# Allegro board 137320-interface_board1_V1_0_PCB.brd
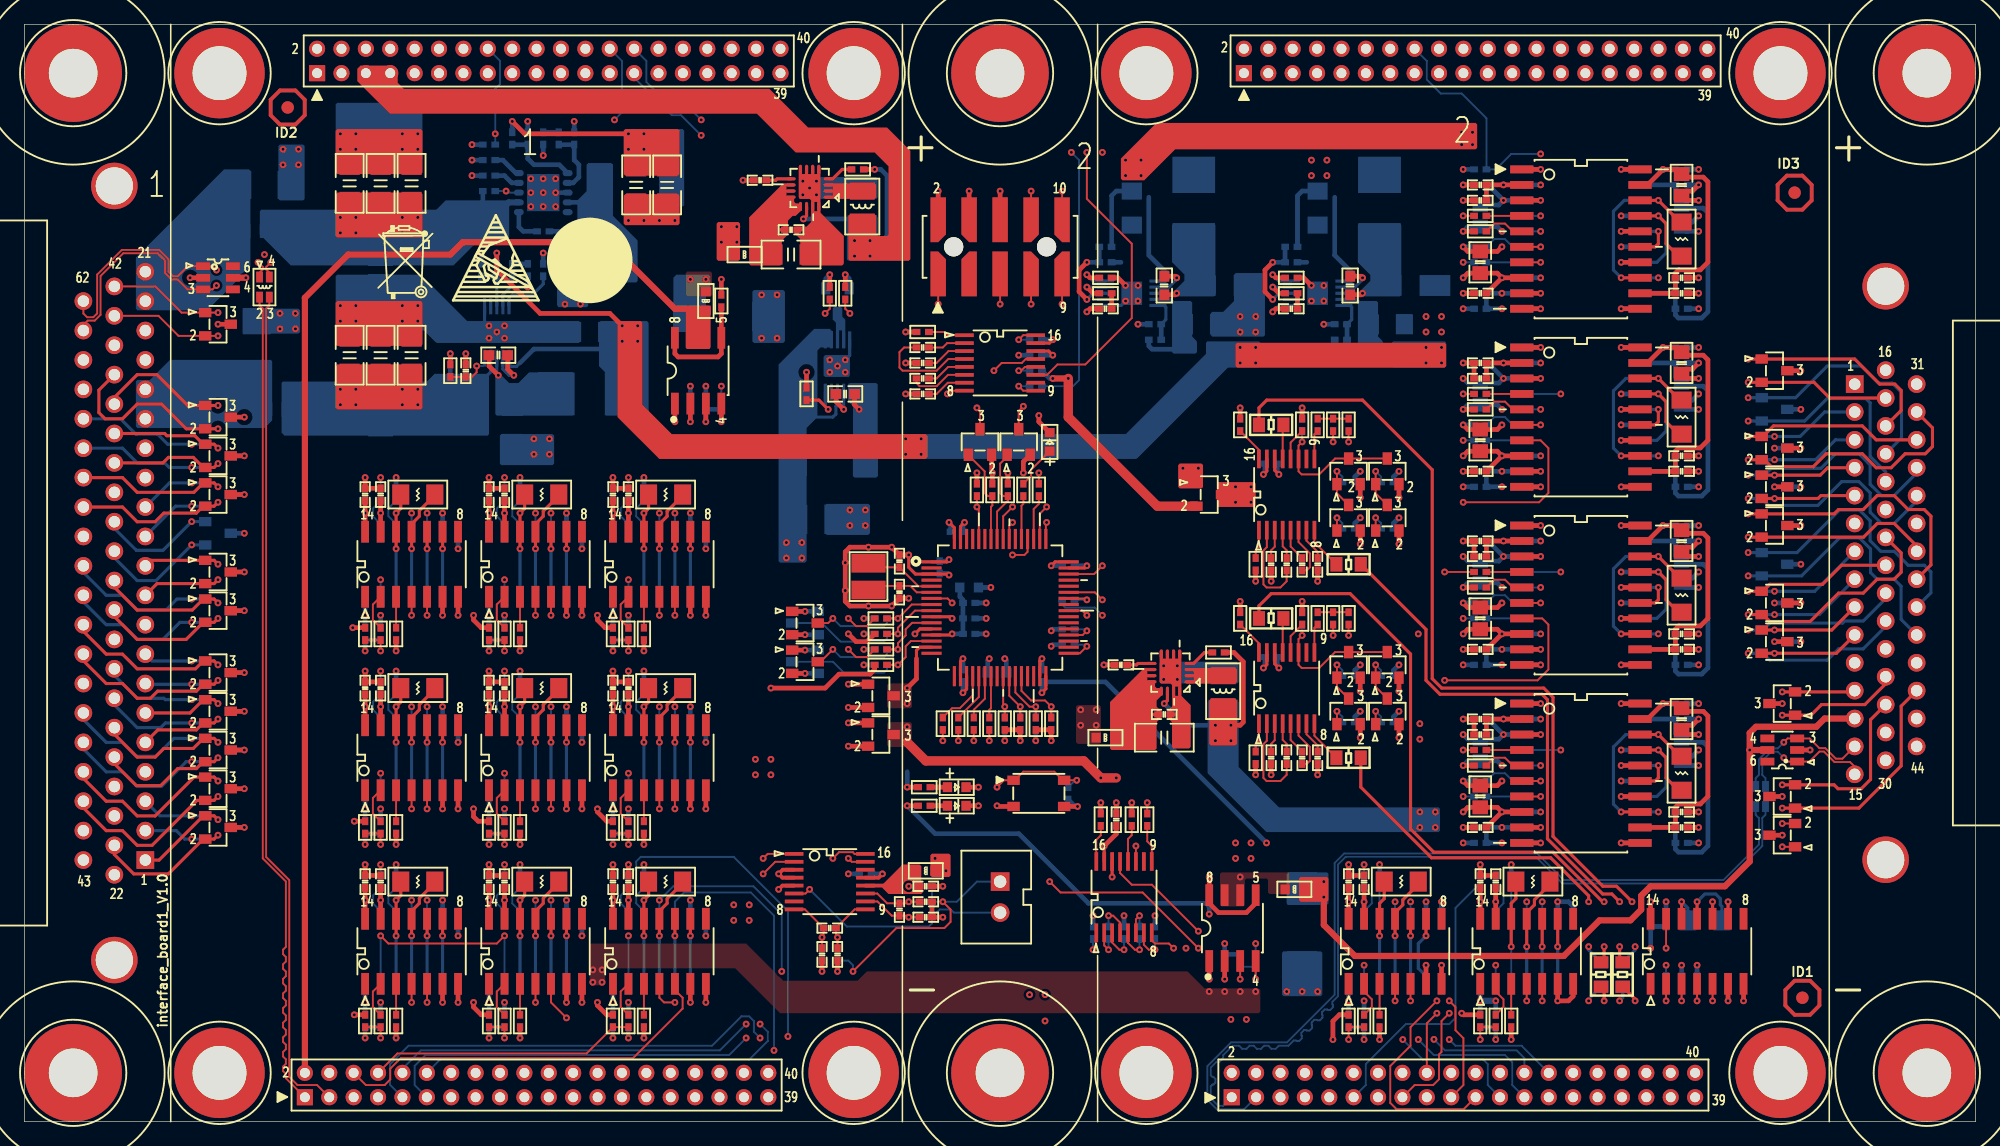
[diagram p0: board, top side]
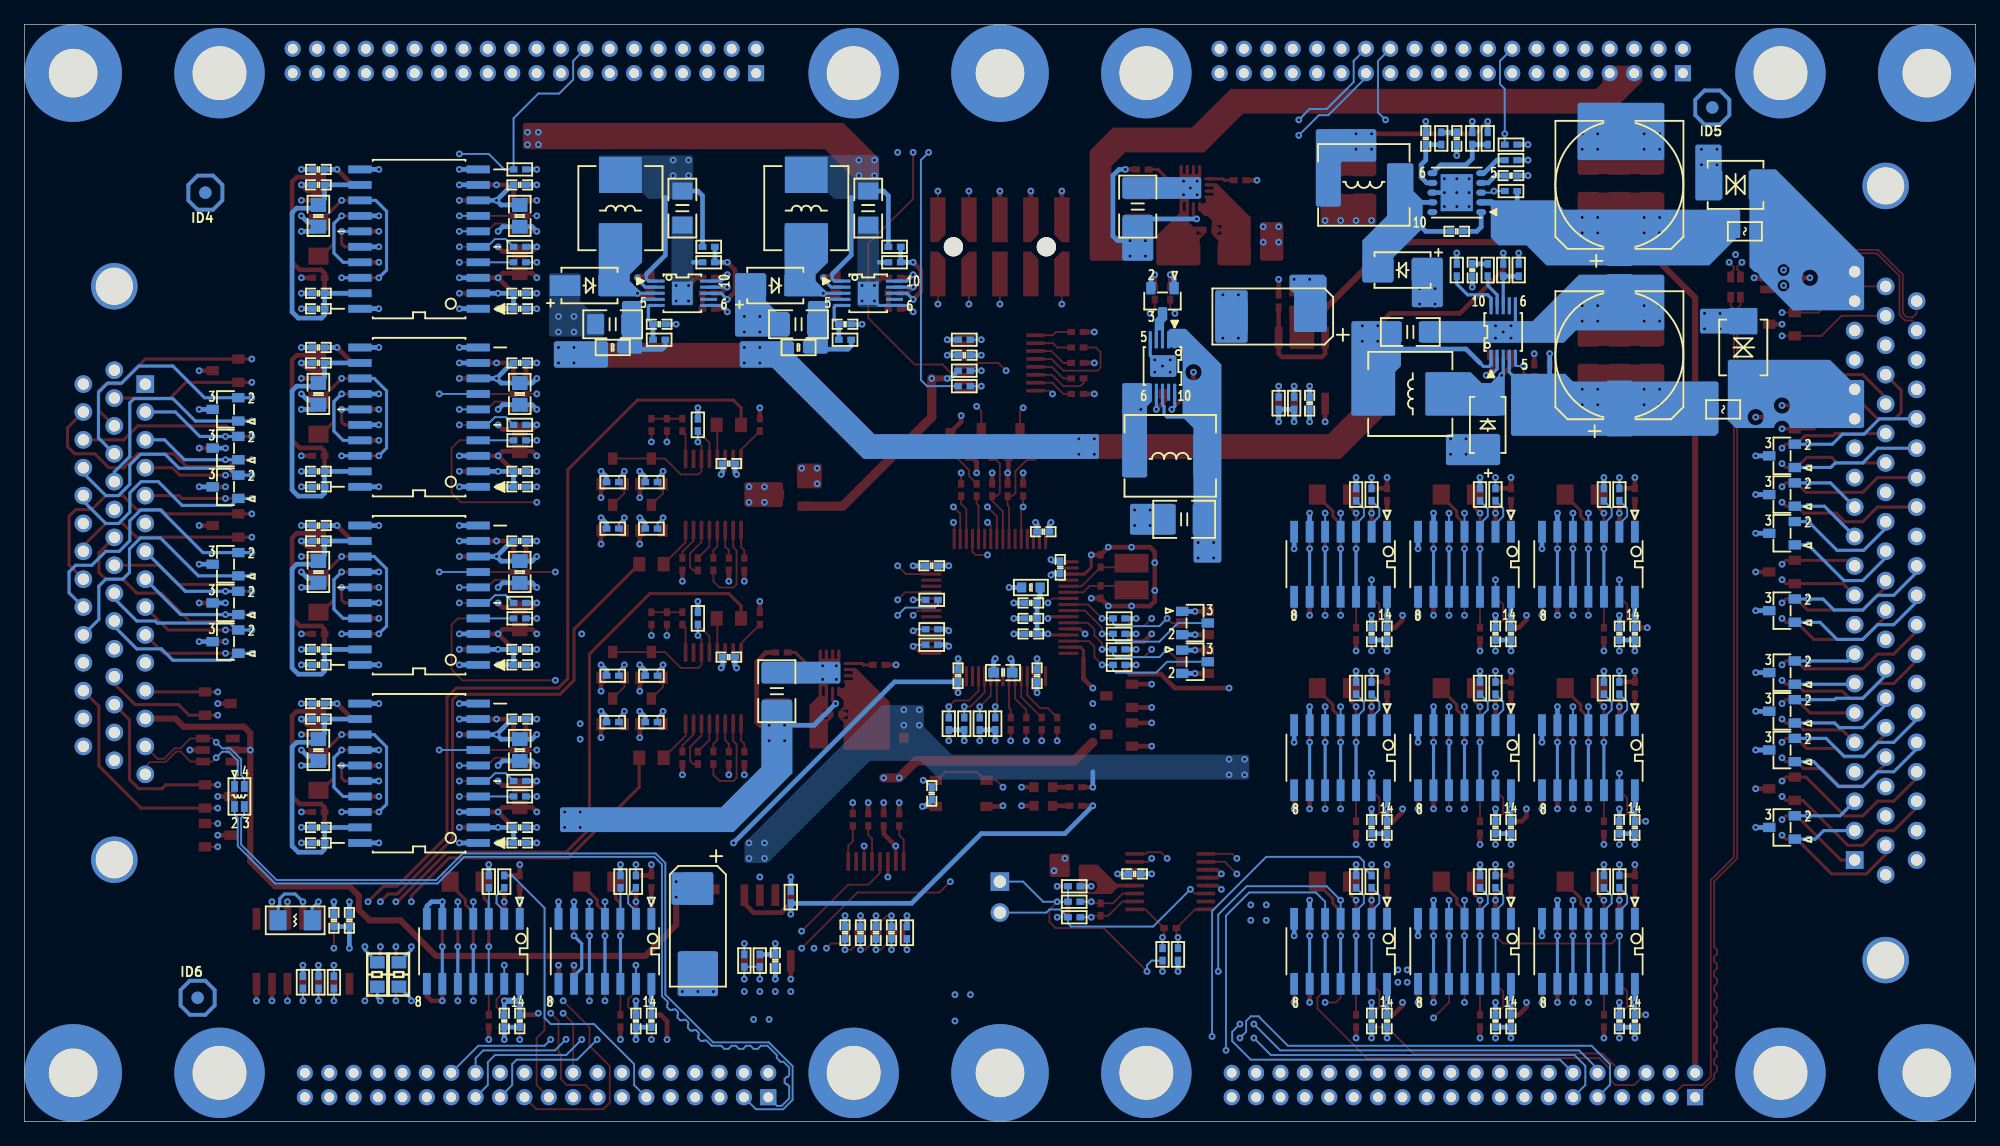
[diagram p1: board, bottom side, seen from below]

Outline 160 x 90 mm; copper layers: TOP, GND02, ART03, ART04, POWER05, BOTTOM. Coordinates in mm from the lower left corner of the outline.
Outline path: 0,90 0,0 160,0 160,90 0,90

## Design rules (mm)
net group DIFFPAIR0: nets CON_MAIN_USB_N CON_MAIN_USB_P
net group DIFFPAIR1: nets MAIN_USB_DN MAIN_USB_DP
net group DIFFPAIR2: nets CON_SPARE_USB_N CON_SPARE_USB_P
net group DIFFPAIR3: nets SPARE_USB_DN SPARE_USB_DP

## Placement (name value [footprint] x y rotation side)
C1  100u  [AEC10_5X10_5-G]  29.21 76.83 90 bottom
C2  0.1u  [C0402]  42.55 73.03 0 bottom
C3  4.7u  [C1206]  31.75 76.96 90 top
C4  4.7u  [C1206]  29.21 76.96 90 top
C5  4.7u  [C1206]  26.67 76.96 90 top
C6  47u  [C1206]  52.7 76.83 270 top
C7  47u  [C1206]  50.16 76.83 270 top
C8  0.01u  [C0402]  42.55 80.64 270 bottom
C9  12p  [C0402]  45.09 80.64 90 bottom
C10  0.01u  [C0402]  38.1 77.6 180 bottom
C11  22u  [C1210]  68.71 75.06 90 bottom
C12  47u  [C1206]  62.87 71.12 0 top
C13  0.1u  [C0402]  62.87 73.15 0 top
C14  160p  [C0402]  60.33 77.22 180 top
C15  0.47u  [C0603]  38.86 62.87 180 top
C16  100u  [AEC10_5X10_5-G]  29.21 62.87 90 bottom
C17  4.7u  [C1206]  31.75 62.87 90 top
C18  4.7u  [C1206]  29.21 62.87 90 top
C19  4.7u  [C1206]  26.67 62.87 90 top
C20  0.1u  [C0402]  36.2 61.59 270 top
C21  47u  [C1206]  46.35 64.77 180 bottom
C22  470p  [C0402]  41.27 69.85 270 bottom
C23  0.47u  [C0603]  108.71 68.58 270 top
C24  4.7u  [C1206]  111.76 65.41 0 bottom
C25  0.1u  [C0402]  107.95 65.41 0 bottom
C26  47u  [C1206]  106.05 74.93 270 bottom
C27  470p  [C0402]  103.89 66.67 180 top
C28  0.47u  [C0603]  67.31 59.69 0 top
C29  22u  [C1210]  64.9 49.4 0 bottom
C30  20p  [C0402]  71.75 45.97 90 top
C31  20p  [C0402]  71.75 43.43 270 top
C32  0.1u  [C0402]  85.6 26.92 270 bottom
C33  0.1u  [C0402]  76.96 36.58 90 bottom
C34  0.01u  [C0402]  77.47 40.01 0 bottom
C35  0.1u  [C0402]  77.47 41.27 0 bottom
C36  1u  [C0402]  77.47 42.55 0 bottom
C37  0.1u  [C0402]  83.44 36.58 90 bottom
C38  0.1u  [C0402]  85.6 45.59 0 bottom
C39  0.1u  [C0402]  76.45 48.39 0 bottom
C40  0.1u  [C0402]  75.06 45.47 270 bottom
C41  4.7u  [C0603]  79.76 36.83 0 bottom
C42  0.01u  [C0402]  73.91 18.03 0 top
C43  0.1u  [C0402]  71.75 17.4 90 top
C44  0.1u  [C0402]  133.35 16.51 270 bottom
C45  0.1u  [C0402]  134.62 16.51 270 bottom
C46  0.01u  [C0402]  73.91 16.76 0 top
C47  0.01u  [C0402]  66.67 13.72 270 top
C48  0.1u  [C0402]  66.04 15.88 0 top
C49  0.01u  [C0402]  65.41 13.72 270 top
C50  0.1u  [C0402]  73.91 19.3 0 top
C51  0.1u  [C0402]  68.96 20.32 180 bottom
C52  22u  [C1210]  98.3 35.31 90 bottom
C53  47u  [C1206]  93.47 31.5 0 top
C54  0.1u  [C0402]  93.47 33.4 0 top
C55  160p  [C0402]  89.92 37.47 180 top
C56  0.47u  [C0603]  93.47 68.58 270 top
C57  4.7u  [C1206]  96.52 65.41 0 bottom
C58  470p  [C0402]  88.65 66.67 180 top
C59  0.1u  [C0402]  92.71 65.41 0 bottom
C60  47u  [C1206]  90.81 74.93 270 bottom
C61  0.1u  [C0402]  29.21 51.44 90 top
C62  0.1u  [C0402]  27.94 51.44 90 top
C63  0.1u  [C0402]  29.21 40.01 270 bottom
C64  0.1u  [C0402]  27.94 40.01 270 bottom
C65  0.1u  [C0402]  39.37 51.44 90 top
C66  0.1u  [C0402]  38.1 51.44 90 top
C67  0.1u  [C0402]  39.37 40.01 270 bottom
C68  0.1u  [C0402]  38.1 40.01 270 bottom
C69  0.1u  [C0402]  49.53 51.44 90 top
C70  0.1u  [C0402]  48.26 51.44 90 top
C71  0.1u  [C0402]  48.26 40.01 270 bottom
C72  0.1u  [C0402]  49.53 40.01 270 bottom
C73  0.1u  [C0402]  29.21 35.56 90 top
C74  0.1u  [C0402]  27.94 35.56 90 top
C75  0.1u  [C0402]  29.21 24.13 270 bottom
C76  0.1u  [C0402]  27.94 24.13 270 bottom
C77  0.1u  [C0402]  39.37 35.56 90 top
C78  0.1u  [C0402]  38.1 35.56 90 top
C79  0.1u  [C0402]  38.1 24.13 270 bottom
C80  0.1u  [C0402]  39.37 24.13 270 bottom
C81  0.1u  [C0402]  49.53 35.56 90 top
C82  0.1u  [C0402]  48.26 35.56 90 top
C83  0.1u  [C0402]  49.53 24.13 270 bottom
C84  0.1u  [C0402]  48.26 24.13 270 bottom
C85  0.1u  [C0402]  29.21 19.68 90 top
C86  0.1u  [C0402]  27.94 19.68 90 top
C87  0.1u  [C0402]  29.21 8.26 270 bottom
C88  0.1u  [C0402]  27.94 8.26 270 bottom
C89  0.1u  [C0402]  39.37 19.68 90 top
C90  0.1u  [C0402]  38.1 19.68 90 top
C91  0.1u  [C0402]  39.37 8.26 270 bottom
C92  0.1u  [C0402]  38.1 8.26 270 bottom
C93  0.1u  [C0402]  49.53 19.68 90 top
C94  0.1u  [C0402]  48.26 19.68 90 top
C95  0.1u  [C0402]  48.26 8.26 270 bottom
C96  0.1u  [C0402]  49.53 8.26 270 bottom
C129  10u  [C0805]  119.38 26.67 90 top
C130  0.1u  [C0402]  119.38 33.02 180 top
C131  0.01u  [C0402]  119.38 24.13 180 top
C132  0.1u  [C0402]  119.38 31.75 180 top
C133  10u  [C0805]  135.89 33.02 270 top
C134  0.1u  [C0402]  135.89 25.4 0 top
C135  0.01u  [C0402]  135.89 24.13 0 top
C136  0.1u  [C0402]  135.89 34.29 0 bottom
C137  0.1u  [C0402]  119.38 24.13 180 bottom
C138  10u  [C0805]  119.38 30.48 270 bottom
C139  0.1u  [C0402]  119.38 22.86 180 bottom
C140  0.01u  [C0402]  119.38 33.02 180 bottom
C141  10u  [C0805]  135.89 30.48 270 bottom
C142  0.1u  [C0402]  135.89 33.02 0 bottom
C143  0.01u  [C0402]  135.89 22.86 0 bottom
C144  0.1u  [C0402]  135.89 24.13 0 bottom
C145  10u  [C0805]  119.38 74.3 270 bottom
C146  0.1u  [C0402]  119.38 67.94 180 bottom
C147  0.01u  [C0402]  119.38 76.83 180 bottom
C148  0.1u  [C0402]  119.38 66.67 180 bottom
C149  10u  [C0805]  135.89 74.3 270 bottom
C150  0.1u  [C0402]  135.89 67.94 0 bottom
C151  0.01u  [C0402]  135.89 66.67 0 bottom
C152  0.1u  [C0402]  135.89 76.83 0 bottom
C153  10u  [C0805]  119.38 70.48 90 top
C154  0.1u  [C0402]  119.38 76.83 180 top
C155  0.01u  [C0402]  119.38 67.94 180 top
C156  0.1u  [C0402]  119.38 75.56 180 top
C157  10u  [C0805]  135.89 76.83 270 top
C158  0.1u  [C0402]  135.89 78.11 0 bottom
C159  0.01u  [C0402]  135.89 67.94 0 top
C160  0.1u  [C0402]  135.89 69.22 0 top
C161  10u  [C0805]  119.38 41.27 90 top
C162  0.1u  [C0402]  119.38 46.35 180 top
C163  0.01u  [C0402]  119.38 38.73 180 top
C164  0.1u  [C0402]  119.38 47.62 180 top
C165  10u  [C0805]  135.89 47.62 270 top
C166  0.1u  [C0402]  135.89 48.9 0 bottom
C167  0.01u  [C0402]  135.89 38.73 0 top
C168  0.1u  [C0402]  135.89 40.01 0 top
C169  10u  [C0805]  119.38 45.09 270 bottom
C170  0.01u  [C0402]  119.38 47.62 180 bottom
C171  0.1u  [C0402]  119.38 38.73 180 bottom
C172  0.1u  [C0402]  119.38 37.47 180 bottom
C173  10u  [C0805]  135.89 45.09 270 bottom
C174  0.1u  [C0402]  135.89 38.73 0 bottom
C175  0.01u  [C0402]  135.89 37.47 0 bottom
C176  0.1u  [C0402]  135.89 47.62 0 bottom
C177  10u  [C0805]  119.38 55.88 90 top
C178  0.1u  [C0402]  119.38 60.96 180 top
C179  0.01u  [C0402]  119.38 53.34 180 top
C180  0.1u  [C0402]  119.38 62.23 180 top
C181  10u  [C0805]  135.89 62.23 270 top
C182  0.1u  [C0402]  135.89 63.5 0 bottom
C183  0.01u  [C0402]  135.89 53.34 0 top
C184  0.1u  [C0402]  135.89 54.61 0 top
C185  10u  [C0805]  119.38 59.69 270 bottom
C186  0.1u  [C0402]  119.38 52.07 180 bottom
C187  0.01u  [C0402]  119.38 62.23 180 bottom
C188  0.1u  [C0402]  119.38 53.34 180 bottom
C189  10u  [C0805]  135.89 59.69 270 bottom
C190  0.1u  [C0402]  135.89 53.34 0 bottom
C191  0.01u  [C0402]  135.89 52.07 0 bottom
C192  0.1u  [C0402]  135.89 62.23 0 bottom
C193  0.1u  [C0402]  82.93 62.87 0 bottom
C194  0.1u  [C0402]  73.66 63.5 180 top
C195  0.1u  [C0402]  73.66 60.96 180 top
C196  0.1u  [C0402]  73.66 59.69 180 top
C197  0.1u  [C0402]  73.66 62.23 180 top
C198  0.1u  [C0402]  89.53 24.77 90 top
C199  0.1u  [C0402]  88.9 15.49 90 bottom
C200  0.1u  [C0402]  91.44 15.49 90 bottom
C201  0.1u  [C0402]  92.71 15.49 90 bottom
C202  0.1u  [C0402]  90.17 15.49 90 bottom
C203  220u  [TC7343]  57.78 66.04 0 bottom
C204  0.1u  [C0402]  54.61 58.93 90 bottom
C205  220u  [TC7343]  104.78 15.88 270 bottom
C206  0.1u  [C0402]  98.42 13.21 90 bottom
C207  0.1u  [C0402]  109.86 19.68 90 top
C208  0.1u  [C0402]  109.86 8.26 270 bottom
C209  0.1u  [C0402]  108.58 19.68 90 top
C210  0.1u  [C0402]  108.58 8.26 270 bottom
C211  0.1u  [C0402]  120.65 19.68 90 top
C212  0.1u  [C0402]  120.65 8.26 270 bottom
C213  0.1u  [C0402]  119.38 19.68 90 top
C214  0.1u  [C0402]  119.38 8.26 270 bottom
C215  0.1u  [C0402]  106.05 29.84 270 top
C216  0.1u  [C0402]  102.23 38.1 0 bottom
C217  0.1u  [C0402]  103.5 29.84 90 top
C218  0.1u  [C0402]  104.78 29.84 270 top
C219  0.1u  [C0402]  102.23 29.84 270 top
C220  0.1u  [C0402]  106.05 45.72 270 top
C221  0.1u  [C0402]  102.23 53.98 0 bottom
C222  0.1u  [C0402]  103.5 45.72 90 top
C223  0.1u  [C0402]  104.78 45.72 270 top
C224  0.1u  [C0402]  102.23 45.72 270 top
D1  SMBJ36CA  [DO-214AA_SMB]  19.68 76.83 0 bottom
D2  B350A-13-F  [SMA]  46.99 69.85 0 bottom
D3  APT1608SYCK  [D0603]  76.45 27.43 0 top
D4  SMBJ36CA  [DO-214AA_SMB]  19.05 63.5 90 bottom
D5  B350A-13-F  [SMA]  40.01 57.15 90 bottom
D6  APT1608SYCK  [D0603]  76.45 25.91 0 top
D7  B350A-13-F  [SMA]  113.67 68.58 180 bottom
D8  BAV170Q-7-F  [SOT23-3-095-3X1_4]  66.67 67.31 0 bottom
D9  BAT54S  [SOT23-3-095-3X1_4]  64.01 40.89 270 top
D10  BAT54S  [SOT23-3-095-3X1_4]  64.01 40.89 270 bottom
D11  BAT54S  [SOT23-3-095-3X1_4]  70.23 31.75 270 top
D12  BAT54S  [SOT23-3-095-3X1_4]  70.23 34.92 270 top
D13  BAT54S  [SOT23-3-095-3X1_4]  64.01 37.72 270 bottom
D14  BAT54S  [SOT23-3-095-3X1_4]  64.01 37.72 270 top
D15  APT1608SYCK  [D0603]  84.07 55.75 90 top
D16  CDSOT23-T24CAN  [SOT23-3-095-3X1_4]  144.15 34.29 90 top
D17  CDSOT23-T24CAN  [SOT23-3-095-3X1_4]  144.15 26.67 90 top
D18  B350A-13-F  [SMA]  98.42 68.58 180 bottom
D19  CDSOT23-T24CAN  [SOT23-3-095-3X1_4]  15.88 57.78 270 top
D20  CDSOT23-T24CAN  [SOT23-3-095-3X1_4]  15.88 54.61 270 top
D21  CDSOT23-T24CAN  [SOT23-3-095-3X1_4]  15.88 54.61 90 bottom
D22  CDSOT23-T24CAN  [SOT23-3-095-3X1_4]  15.88 51.44 270 top
D23  CDSOT23-T24CAN  [SOT23-3-095-3X1_4]  15.88 51.44 90 bottom
D24  CDSOT23-T24CAN  [SOT23-3-095-3X1_4]  15.88 45.09 270 top
D25  CDSOT23-T24CAN  [SOT23-3-095-3X1_4]  15.88 48.26 90 bottom
D26  CDSOT23-T24CAN  [SOT23-3-095-3X1_4]  15.88 41.91 270 top
D27  CDSOT23-T24CAN  [SOT23-3-095-3X1_4]  15.88 41.91 90 bottom
D28  CDSOT23-T24CAN  [SOT23-3-095-3X1_4]  15.88 36.83 270 top
D29  CDSOT23-T24CAN  [SOT23-3-095-3X1_4]  15.88 36.83 90 bottom
D30  CDSOT23-T24CAN  [SOT23-3-095-3X1_4]  15.88 33.66 270 top
D31  CDSOT23-T24CAN  [SOT23-3-095-3X1_4]  15.88 33.66 90 bottom
D32  CDSOT23-T24CAN  [SOT23-3-095-3X1_4]  15.88 30.48 270 top
D33  CDSOT23-T24CAN  [SOT23-3-095-3X1_4]  15.88 30.48 90 bottom
D34  CDSOT23-T24CAN  [SOT23-3-095-3X1_4]  15.88 27.3 270 top
D35  CDSOT23-T24CAN  [SOT23-3-095-3X1_4]  15.88 24.13 90 bottom
D36  CDSOT23-T24CAN  [SOT23-3-095-3X1_4]  15.88 24.13 270 top
D41  CDSOT23-T24CAN  [SOT23-3-095-3X1_4]  143.51 39.37 90 bottom
D42  CDSOT23-T24CAN  [SOT23-3-095-3X1_4]  143.51 42.55 270 top
D43  CDSOT23-T24CAN  [SOT23-3-095-3X1_4]  143.51 58.42 90 bottom
D44  CDSOT23-T24CAN  [SOT23-3-095-3X1_4]  143.51 61.59 270 top
D45  CDSOT23-T24CAN  [SOT23-3-095-3X1_4]  143.51 45.72 90 bottom
D46  CDSOT23-T24CAN  [SOT23-3-095-3X1_4]  143.51 48.9 270 top
D47  CDSOT23-T24CAN  [SOT23-3-095-3X1_4]  143.51 52.07 90 bottom
D48  CDSOT23-T24CAN  [SOT23-3-095-3X1_4]  143.51 55.24 270 top
D49  CDSOT23-T24CAN  [SOT23-3-095-3X1_4]  15.88 65.41 270 top
D50  CDSOT23-T24CAN  [SOT23-3-095-3X1_4]  144.15 23.5 90 top
D51  CDSOT23-T24CAN  [SOT23-3-095-3X1_4]  143.51 39.37 270 top
D52  CDSOT23-T24CAN  [SOT23-3-095-3X1_4]  143.51 42.55 90 bottom
D53  CDSOT23-T24CAN  [SOT23-3-095-3X1_4]  143.51 55.24 90 bottom
D54  CDSOT23-T24CAN  [SOT23-3-095-3X1_4]  143.51 52.07 270 top
D55  BAV170Q-7-F  [SOT23-3-095-3X1_4]  97.16 51.44 270 top
F1  0467003  [F0603]  18.92 73.03 0 bottom
F2  0467003  [F0603]  20.7 58.42 0 bottom
FB1  BLM18PG121SH1D  [FB0603]  59.05 71.12 0 top
FB2  BLM18PG121SH1D  [FB0603]  111.76 63.5 180 bottom
FB3  BLM18PG121SH1D  [FB0603]  77.47 43.81 0 bottom
FB4  BLM18PG121SH1D  [FB0603]  73.91 20.57 180 top
FB5  BLM18PG121SH1D  [FB0603]  88.65 31.5 0 top
FB6  BLM18PG121SH1D  [FB0603]  96.52 63.5 180 bottom
FB7  BLM18PG121SH1D  [FB0603]  55.88 67.31 270 top
FB8  BLM18PG121SH1D  [FB0603]  104.14 19.05 180 top
H1  MH-7R4D3R2  [HOLE315-157]  4 86 0 top
H2  MH-7R4D3R2  [HOLE315-157]  4 4 0 top
H3  MH-7R4D3R2  [HOLE315-157]  80 86 0 top
H4  MH-7R4D3R2  [HOLE315-157]  80 4 0 top
H5  MH-7R4D3R2  [HOLE315-157]  156 86 0 top
H6  MH-7R4D3R2  [HOLE315-157]  156 4 0 top
J1  181-M62-213R141  [DB62-3CF]  -0.7 45 270 top
J2  181-M44-213R141  [DB44-3CF]  160.7 45 90 top
J3  791077069  [HD40-2_0-40_19X4_19-H4_44]  43 87 0 top
J4  791077069  [HD40-2_0-40_19X4_19-H4_44]  42 3 0 top
J5  791077069  [HD40-2_0-40_19X4_19-H4_44]  119 87 0 top
J6  791077069  [HD40-2_0-40_19X4_19-H4_44]  118 3 0 top
J8  0901311081  [SIP2-2_54]  80.01 18.41 90 top
J9  15-91-0100  [SHD10-2_54]  80.01 71.75 0 top
L1  15uH  [L7567]  50.16 76.83 0 bottom
L2  2.2uH  [L1008]  68.71 75.06 270 top
L3  6.8uH  [IND_74437349047]  46.35 59.69 0 bottom
L4  6.8uH  [IND_74437349047]  111.12 74.93 90 bottom
L5  15uH  [L7567]  66.04 54.61 180 bottom
L6  2.2uH  [L1008]  98.3 35.31 270 top
L7  6.8uH  [IND_74437349047]  95.89 74.93 90 bottom
L8  ACM2012H  [L4-0805]  19.68 68.45 270 top
L9  ACM2012H  [L4-0805]  142.37 26.67 270 bottom
NOREF  -  []  459.86 210.4 0 top
NOREF#2  -  []  459.86 202.78 0 top
NOREF#3  -  []  247.78 -1.91 0 top
NOREF#4  -  []  434.46 210.4 0 top
NOREF#5  -  []  37.97 70.36 0 top
NOREF#6  -  []  257.81 174.75 0 top
NOREF#7  -  [unnamed#2]  21.59 83.19 0 top
NOREF#8  -  []  46.86 70.87 0 top
NOREF#9  -  []  434.46 195.16 0 top
NOREF#10  -  []  -19.05 -43.18 0 top
NOREF#11  -  [unnamed#2]  145.8 10.16 0 top
NOREF#12  -  []  459.86 195.16 0 top
NOREF#13  -  []  33.78 70.61 0 top
NOREF#14  -  []  281.94 109.98 0 top
NOREF#15  -  []  434.46 202.78 0 top
NOREF#16  -  [unnamed#2]  145.16 76.2 0 top
NOREF#17  -  []  247.9 52.96 0 top
NOREF#18  -  [unnamed#2]  145.8 10.16 180 bottom
NOREF#19  -  [unnamed#2]  145.16 76.2 180 bottom
NOREF#20  -  [unnamed#2]  21.59 83.19 180 bottom
Q1  2N7002ET1G  [SOT23-3-095-3X1_4]  81.53 55.75 0 top
Q2  2N7002ET1G  [SOT23-3-095-3X1_4]  78.36 55.75 0 top
Q3  2N7002ET1G  [SOT23-3-095-3X1_4]  111.76 33.66 0 top
Q4  2N7002ET1G  [SOT23-3-095-3X1_4]  111.76 37.47 0 top
Q5  2N7002ET1G  [SOT23-3-095-3X1_4]  108.58 33.66 0 top
Q6  2N7002ET1G  [SOT23-3-095-3X1_4]  108.58 37.47 0 top
Q7  2N7002ET1G  [SOT23-3-095-3X1_4]  111.76 49.53 0 top
Q8  2N7002ET1G  [SOT23-3-095-3X1_4]  111.76 53.34 0 top
Q9  2N7002ET1G  [SOT23-3-095-3X1_4]  108.58 49.53 0 top
Q10  2N7002ET1G  [SOT23-3-095-3X1_4]  108.58 53.34 0 top
R1  4.7K  [R0402]  38.1 80.14 0 bottom
R2  4.7K  [R0402]  119.38 78.11 0 bottom
R3  10K  [R0402]  38.1 76.33 0 bottom
R4  10K  [R0402]  43.81 80.64 270 bottom
R5  60.4k  [R0402]  40.01 80.64 270 bottom
R6  4.7K  [R0402]  73.79 27.43 0 top
R7  200k  [R0402]  38.1 78.87 180 bottom
R8  11.5k  [R0402]  41.27 80.64 90 bottom
R9  4.7K  [R0402]  68.33 78.11 0 top
R10  10K  [R0402]  34.92 61.59 270 top
R11  16.2k  [R0402]  40.01 69.85 90 bottom
R12  536k  [R0402]  38.73 69.85 270 bottom
R13  4.7K  [R0402]  73.79 25.91 0 top
R14  68.1k  [R0402]  42.55 69.85 90 bottom
R15  100K  [R0402]  37.47 69.85 90 bottom
R16  10K  [R0402]  107.95 64.14 0 bottom
R17  20k  [R0402]  103.89 67.94 0 top
R18  316k  [R0402]  103.89 71.75 180 bottom
R19  68.1k  [R0402]  103.89 69.22 0 top
R20  100K  [R0402]  103.89 70.48 0 bottom
R21  0  [R0402]  66.04 67.94 90 top
R22  0  [R0402]  67.31 67.94 90 top
R23  215k  [R0402]  64.14 59.69 90 top
R24  1K  [R0402]  70.23 41.27 0 bottom
R25  10K  [R0402]  70.23 41.27 0 top
R26  10K  [R0402]  70.23 40.01 0 top
R27  10K  [R0402]  70.23 40.01 0 bottom
R28  33  [R0402]  75.31 32.64 90 top
R29  33  [R0402]  76.58 32.64 90 top
R30  1K  [R0402]  70.23 38.73 0 bottom
R31  10K  [R0402]  70.23 38.73 0 top
R32  10K  [R0402]  70.23 37.47 0 top
R33  0  [R0402]  77.85 32.64 90 top
R34  33  [R0402]  79.12 32.64 90 top
R35  10K  [R0402]  70.23 37.47 0 bottom
R36  33  [R0402]  85.6 42.8 180 bottom
R37  10K  [R0402]  85.6 39.12 0 bottom
R38  10K  [R0402]  78.11 51.82 90 top
R39  10K  [R0402]  85.6 40.39 0 bottom
R40  33  [R0402]  83.19 51.82 270 top
R41  4.7K  [R0402]  81.92 51.82 90 top
R42  4.7K  [R0402]  80.64 51.82 90 top
R43  4.7K  [R0402]  79.38 51.82 90 top
R44  4.7K  [R0402]  135.89 11.43 90 bottom
R45  120  [R1206]  137.79 16.51 0 bottom
R46  33  [R0402]  134.62 11.43 270 bottom
R47  1K  [R0402]  73.91 18.03 180 bottom
R48  1K  [R0402]  73.91 16.76 180 bottom
R49  1K  [R0402]  137.16 11.43 90 bottom
R50  1K  [R0402]  66.67 13.72 90 bottom
R51  1.65k  [R0402]  73.91 19.3 180 bottom
R52  1K  [R0402]  65.41 13.72 90 bottom
R53  4.7K  [R0402]  97.92 38.48 0 top
R54  10K  [R0402]  92.71 64.14 0 bottom
R55  20k  [R0402]  88.65 67.94 0 top
R56  316k  [R0402]  88.65 71.75 180 bottom
R57  68.1k  [R0402]  88.65 69.22 0 top
R58  100K  [R0402]  88.65 70.48 0 bottom
R59  4.7K  [R0402]  30.48 40.01 270 top
R60  120  [R1206]  32.26 51.44 0 top
R61  2.7k  [R0402]  29.21 40.01 90 top
R62  4.7K  [R0402]  27.94 40.01 90 top
R63  4.7K  [R0402]  30.48 51.44 90 bottom
R64  33  [R0402]  29.21 51.44 270 bottom
R65  4.7K  [R0402]  40.64 40.01 270 top
R66  120  [R1206]  42.42 51.44 0 top
R67  4.7K  [R0402]  38.1 40.01 90 top
R68  2.7k  [R0402]  39.37 40.01 90 top
R69  4.7K  [R0402]  40.64 51.44 90 bottom
R70  33  [R0402]  39.37 51.44 270 bottom
R71  4.7K  [R0402]  50.8 40.01 270 top
R72  120  [R1206]  52.58 51.44 0 top
R73  4.7K  [R0402]  48.26 40.01 90 top
R74  2.7k  [R0402]  49.53 40.01 90 top
R75  4.7K  [R0402]  50.8 51.44 90 bottom
R76  33  [R0402]  49.53 51.44 270 bottom
R77  4.7K  [R0402]  30.48 24.13 270 top
R78  4.7K  [R0402]  27.94 24.13 90 top
R79  2.7k  [R0402]  29.21 24.13 90 top
R80  120  [R1206]  32.26 35.56 0 top
R81  4.7K  [R0402]  30.48 35.56 90 bottom
R82  33  [R0402]  29.21 35.56 270 bottom
R83  4.7K  [R0402]  40.64 24.13 270 top
R84  2.7k  [R0402]  39.37 24.13 90 top
R85  120  [R1206]  42.42 35.56 0 top
R86  4.7K  [R0402]  38.1 24.13 90 top
R87  4.7K  [R0402]  40.64 35.56 90 bottom
R88  33  [R0402]  39.37 35.56 270 bottom
R89  4.7K  [R0402]  50.8 24.13 270 top
R90  2.7k  [R0402]  49.53 24.13 90 top
R91  120  [R1206]  52.58 35.56 0 top
R92  4.7K  [R0402]  48.26 24.13 90 top
R93  4.7K  [R0402]  50.8 35.56 90 bottom
R94  33  [R0402]  49.53 35.56 270 bottom
R95  4.7K  [R0402]  30.48 8.26 270 top
R96  120  [R1206]  32.26 19.68 0 top
R97  4.7K  [R0402]  27.94 8.26 90 top
R98  2.7k  [R0402]  29.21 8.26 90 top
R99  4.7K  [R0402]  30.48 19.68 90 bottom
R100  33  [R0402]  29.21 19.68 270 bottom
R101  4.7K  [R0402]  40.64 8.26 270 top
R102  120  [R1206]  42.42 19.68 0 top
R103  4.7K  [R0402]  38.1 8.26 90 top
R104  2.7k  [R0402]  39.37 8.26 90 top
R105  4.7K  [R0402]  40.64 19.68 90 bottom
R106  33  [R0402]  39.37 19.68 270 bottom
R107  4.7K  [R0402]  50.8 8.26 270 top
R108  2.7k  [R0402]  49.53 8.26 90 top
R109  120  [R1206]  52.58 19.68 0 top
R110  4.7K  [R0402]  48.26 8.26 90 top
R111  4.7K  [R0402]  50.8 19.68 90 bottom
R112  33  [R0402]  49.53 19.68 270 bottom
R123  33  [R0402]  119.38 30.48 0 top
R124  120  [R1206]  135.89 28.57 270 top
R125  4.7K  [R0402]  119.38 29.21 180 top
R126  33  [R0402]  119.38 26.67 0 bottom
R127  4.7K  [R0402]  119.38 27.94 180 bottom
R128  33  [R0402]  119.38 70.48 0 bottom
R129  120  [R1206]  135.89 72.39 270 top
R130  4.7K  [R0402]  119.38 71.75 180 bottom
R131  33  [R0402]  119.38 74.3 0 top
R132  4.7K  [R0402]  119.38 73.03 180 top
R133  33  [R0402]  119.38 45.09 0 top
R134  120  [R1206]  135.89 43.18 270 top
R135  4.7K  [R0402]  119.38 43.81 180 top
R136  33  [R0402]  119.38 41.27 0 bottom
R137  4.7K  [R0402]  119.38 42.55 180 bottom
R138  33  [R0402]  119.38 59.69 0 top
R139  120  [R1206]  135.89 57.78 270 top
R140  4.7K  [R0402]  119.38 58.42 180 top
R141  33  [R0402]  119.38 55.88 0 bottom
R142  4.7K  [R0402]  119.38 57.15 180 bottom
R143  10K  [R0402]  82.93 61.59 180 bottom
R144  10K  [R0402]  82.93 64.14 180 bottom
R145  33  [R0402]  82.93 60.33 180 bottom
R146  10K  [R0402]  73.66 64.77 180 top
R147  10K  [R0402]  88.27 24.77 270 top
R148  10K  [R0402]  90.81 24.77 270 top
R149  33  [R0402]  92.08 24.77 270 top
R150  10K  [R0402]  87.63 15.49 90 bottom
R151  10K  [R0402]  57.15 67.31 90 top
R152  0  [R0402]  57.15 58.93 90 bottom
R153  4.7K  [R0402]  55.88 58.93 270 bottom
R154  10K  [R0402]  97.16 18.41 270 bottom
R155  0  [R0402]  100.97 13.21 90 bottom
R156  4.7K  [R0402]  99.69 13.21 270 bottom
R157  4.7K  [R0402]  80.39 32.64 90 bottom
R158  4.7K  [R0402]  80.39 32.64 270 top
R159  4.7K  [R0402]  81.66 32.64 90 bottom
R160  4.7K  [R0402]  81.66 32.64 270 top
R161  4.7K  [R0402]  82.93 32.64 90 bottom
R162  4.7K  [R0402]  82.93 32.64 270 top
R163  4.7K  [R0402]  84.2 32.64 90 bottom
R164  4.7K  [R0402]  84.2 32.64 270 top
R165  4.7K  [R0402]  108.58 8.26 90 top
R166  4.7K  [R0402]  111.12 19.68 90 bottom
R167  4.7K  [R0402]  111.12 8.26 270 top
R168  33  [R0402]  109.86 19.68 270 bottom
R169  2.7k  [R0402]  109.86 8.26 90 top
R170  120  [R1206]  112.9 19.68 0 top
R171  4.7K  [R0402]  121.92 19.68 90 bottom
R172  4.7K  [R0402]  121.92 8.26 270 top
R173  33  [R0402]  120.65 19.68 270 bottom
R174  2.7k  [R0402]  120.65 8.26 90 top
R175  120  [R1206]  123.7 19.68 0 top
R176  4.7K  [R0402]  119.38 8.26 90 top
R177  10K  [R0402]  100.97 29.84 270 top
R178  10K  [R0402]  104.78 41.27 270 top
R179  10K  [R0402]  99.69 41.27 270 top
R180  33  [R0402]  106.05 41.27 270 top
R185  0  [R0402]  107.31 41.27 90 top
R186  0  [R0402]  108.58 41.27 90 top
R187  4.7K  [R0402]  111.76 36.58 0 bottom
R188  4.7K  [R0402]  104.78 41.27 90 bottom
R189  4.7K  [R0402]  108.58 36.58 0 bottom
R190  4.7K  [R0402]  111.76 32.77 180 bottom
R191  4.7K  [R0402]  108.58 32.77 180 bottom
R193  60.4  [R0805]  102.23 41.27 180 top
R194  60.4  [R0805]  108.58 29.84 0 top
R195  4.7K  [R0402]  111.76 52.45 0 bottom
R196  4.7K  [R0402]  104.78 57.15 90 bottom
R197  4.7K  [R0402]  108.58 52.45 0 bottom
R198  4.7K  [R0402]  111.76 48.64 180 bottom
R199  4.7K  [R0402]  108.58 48.64 180 bottom
R200  60.4  [R0805]  102.23 57.15 180 top
R201  60.4  [R0805]  108.58 45.72 0 top
R202  10K  [R0402]  100.97 45.72 270 top
R203  10K  [R0402]  104.78 57.15 270 top
R204  10K  [R0402]  99.69 57.15 270 top
R205  33  [R0402]  106.05 57.15 270 top
R206  0  [R0402]  108.58 57.15 90 top
R207  0  [R0402]  107.31 57.15 90 top
R208  60.4  [R0805]  131.06 12.06 270 bottom
R209  60.4  [R0805]  131.06 12.06 270 top
R210  60.4  [R0805]  129.29 12.06 270 top
R211  60.4  [R0805]  129.29 12.06 270 bottom
SP1  9774040360R  [HOLE292-174]  16 86 0 top
SP2  9774040360R  [HOLE292-174]  68 86 0 top
SP3  9774040360R  [HOLE292-174]  16 4 0 top
SP4  9774040360R  [HOLE292-174]  68 4 0 top
SP5  9774040360R  [HOLE292-174]  92 86 0 top
SP6  9774040360R  [HOLE292-174]  144 86 0 top
SP7  9774040360R  [HOLE292-174]  92 4 0 top
SP8  9774040360R  [HOLE292-174]  144 4 0 top
SW1  PTS810 SJM 250 SMTR LFS  [SW4-0403]  83.19 26.92 0 top
U1  TPS54561DPRR  [SON10-080-0404LH]  42.55 76.2 90 bottom
U2  TPS62142RGTR  [QFN16-050-0303LH]  64.39 76.58 90 top
U3  LT1912EMSE#PBF  [SOP10-0_5-3_1X3_1H-H1_1]  38.73 64.77 180 bottom
U4  LT1912EMSE#PBF  [SOP10-0_5-3_1X3_1H-H1_1]  106.05 67.94 270 bottom
U5  LT3973IMSE-3.3#PBF  [SOP10-0_5-3_1X3_1H-H1_1]  66.67 61.98 0 bottom
U6  STM32F303R8T6  [QFP64-50-1010L]  80.01 42.16 0 top
U7  LTC2864MPS-2#PBF  [SOP14-50-150]  137.16 13.97 0 top
U8  ADS1220IPW  [SOP16-065-4_37]  66.04 19.68 270 top
U9  TPS62142RGTR  [QFN16-050-0303LH]  93.98 36.83 90 top
U10  LT1912EMSE#PBF  [SOP10-0_5-3_1X3_1H-H1_1]  90.81 67.94 270 bottom
U11  SN65HVD1792D  [SOP14-50-150]  31.75 45.72 0 top
U12  LTC2864MPS-2#PBF  [SOP14-50-150]  31.75 45.72 0 bottom
U13  SN65HVD1792D  [SOP14-50-150]  41.91 45.72 0 top
U14  LTC2864MPS-2#PBF  [SOP14-50-150]  41.91 45.72 0 bottom
U15  SN65HVD1792D  [SOP14-50-150]  52.07 45.72 0 top
U16  LTC2864MPS-2#PBF  [SOP14-50-150]  52.07 45.72 0 bottom
U17  SN65HVD1792D  [SOP14-50-150]  31.75 29.84 0 top
U18  LTC2864MPS-2#PBF  [SOP14-50-150]  31.75 29.84 0 bottom
U19  SN65HVD1792D  [SOP14-50-150]  41.91 29.84 0 top
U20  LTC2864MPS-2#PBF  [SOP14-50-150]  41.91 29.84 0 bottom
U21  SN65HVD1792D  [SOP14-50-150]  52.07 29.84 0 top
U22  LTC2864MPS-2#PBF  [SOP14-50-150]  52.07 29.84 0 bottom
U23  SN65HVD1792D  [SOP14-50-150]  31.75 13.97 0 top
U24  LTC2864MPS-2#PBF  [SOP14-50-150]  31.75 13.97 0 bottom
U25  SN65HVD1792D  [SOP14-50-150]  41.91 13.97 0 top
U26  LTC2864MPS-2#PBF  [SOP14-50-150]  41.91 13.97 0 bottom
U27  SN65HVD1792D  [SOP14-50-150]  52.07 13.97 0 top
U28  LTC2864MPS-2#PBF  [SOP14-50-150]  52.07 13.97 0 bottom
U33  ADM2582EBRWZ  [SOP20-1_27-13_0X7_6-H2_65]  127.64 28.57 270 top
U34  ADM2582EBRWZ  [SOP20-1_27-13_0X7_6-H2_65]  127.64 28.57 90 bottom
U35  ADM2582EBRWZ  [SOP20-1_27-13_0X7_6-H2_65]  127.64 72.39 90 bottom
U36  ADM2582EBRWZ  [SOP20-1_27-13_0X7_6-H2_65]  127.64 72.39 270 top
U37  ADM2582EBRWZ  [SOP20-1_27-13_0X7_6-H2_65]  127.64 43.18 270 top
U38  ADM2582EBRWZ  [SOP20-1_27-13_0X7_6-H2_65]  127.64 43.18 90 bottom
U39  ADM2582EBRWZ  [SOP20-1_27-13_0X7_6-H2_65]  127.64 57.78 270 top
U40  ADM2582EBRWZ  [SOP20-1_27-13_0X7_6-H2_65]  127.64 57.78 90 bottom
U41  MAX3221EIPWR  [SOP16-065-4_37]  80.01 62.23 270 top
U42  MAX3221EIPWR  [SOP16-065-4_37]  90.17 18.41 0 top
U43  TPS2042BDR  [SOP8-50-157]  55.24 61.59 0 top
U44  RCLAMP0504S.TCT  [SOT23-6-095-2_9X1_6]  15.88 69.22 270 top
U45  TPS2042BDR  [SOP8-50-157]  99.06 15.88 0 top
U46  RCLAMP0504S.TCT  [SOT23-6-095-2_9X1_6]  144.15 30.48 90 top
U47  SN65HVD1792D  [SOP14-50-150]  112.39 13.97 0 top
U48  LTC2864MPS-2#PBF  [SOP14-50-150]  112.39 13.97 0 bottom
U49  SN65HVD1792D  [SOP14-50-150]  123.19 13.97 0 top
U50  LTC2864MPS-2#PBF  [SOP14-50-150]  123.19 13.97 0 bottom
U51  MAX3221EIPWR  [SOP16-065-4_37]  103.5 35.56 0 top
U52  MAX3221EIPWR  [SOP16-065-4_37]  103.5 51.44 0 top
Y1  8MHz  [X2-3225]  69.22 44.7 90 top

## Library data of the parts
C1 C16 C203 C205 = CAP_POL
C2-C15 C17-C96 C129-C202 C204 C206-C224 = CAP
D1 D4 = DIODE-BI
D2 D5 D7 D18 = DIODE_SCHOTTKY
D3 D6 D15 = LED
D8 D55 = DIODE_DUAL
D9-D14 = DIODE_SCHOTTKY_2
D16 D17 D19-D36 D41-D54 = TVS_ARRAY2
F1 F2 = FUSE
FB1-FB8 = FB
H1-H6 = HOLE
J1 = DSUB-HD-62-R
J2 = DSUB-HD-44-R
J3-J6 = HEADER 20X2
J8 = JUMPER
J9 = HEADER 5X2 SMT
L1-L7 = INDUCTOR
L8 L9 = INDUCTOR-COM
Q1-Q10 = MOSFET_N
R1-R112 R123-R180 R185-R191 R195-R199 R202-R207 = RES
R193 R194 R200 R201 R208-R211 = RES: User Part Number: HAMP; Tolerance: #TOL
SP1-SP8 = SPACER
SW1 = SWITCH-PUSH
U1 = TPS54561
U2 U9 = TPS62140
U3 U4 U10 = LT1912
U5 = LT3973
U6 = STM32F303R8T6
U7 U12 U14 U16 U18 U20 U22 U24 U26 U28 U48 U50 = LTC2864
U8 = ADS1220IPW
U11 U13 U15 U17 U19 U21 U23 U25 U27 U47 U49 = SN65HVD1792
U33-U40 = ADM2582
U41 U42 U51 U52 = MAX3221
U43 U45 = TPS2042
U44 U46 = TVS_ARRAY4_P
Y1 = XTAL

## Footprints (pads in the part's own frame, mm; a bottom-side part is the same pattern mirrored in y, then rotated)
AEC10_5X10_5-G
  rect 4.572x2.032 smd: 1(-4.37,0) 2(4.37,0)
C0402
  rect 0.635x0.508 smd: 1(-0.508,0) 2(0.508,0)
C0603
  rect 0.889x0.813 smd: 1(-0.762,0) 2(0.762,0)
C0805
  rect 1.143x1.27 smd: 1(-0.889,0) 2(0.889,0)
C1206
  rect 1.397x1.651 smd: 1(-1.397,0) 2(1.397,0)
C1210
  rect 1.397x2.413 smd: 1(-1.397,0) 2(1.397,0)
D0603
  rect 0.762x0.813 smd: 1(-0.762,0) 2(0.762,0)
DB44-3CF
  rect 1.448x1.448 hole 0.94: 1(15.494,10.615)
  round 1.448 hole 0.94: 2(13.208,10.615) 3(10.922,10.615) 4(8.636,10.615) 5(6.35,10.615) 6(4.064,10.615) 7(1.778,10.615) 8(-0.508,10.615) 9(-2.794,10.615) 10(-5.08,10.615) 11(-7.366,10.615) 12(-9.652,10.615) 13(-11.938,10.615) 14(-14.224,10.615) 15(-16.51,10.615) 16(16.637,8.075) 17(14.351,8.075) 18(12.065,8.075) 19(9.779,8.075) 20(7.493,8.075) 21(5.207,8.075) 22(2.921,8.075) 23(0.635,8.075) 24(-1.651,8.075) 25(-3.937,8.075) 26(-6.223,8.075) 27(-8.509,8.075) 28(-10.795,8.075) 29(-13.081,8.075) 30(-15.367,8.075) 31(15.494,5.535) 32(13.208,5.535) 33(10.922,5.535) 34(8.636,5.535) 35(6.35,5.535) 36(4.064,5.535) 37(1.778,5.535) 38(-0.508,5.535) 39(-2.794,5.535) 40(-5.08,5.535) 41(-7.366,5.535) 42(-9.652,5.535) 43(-11.938,5.535) 44(-14.224,5.535)
  round 3.81 hole 3.048: 45(-23.52,8.075) 46(23.52,8.075)
DB62-3CF
  rect 1.448x1.448 hole 0.94: 1(23.546,10.615)
  round 1.448 hole 0.94: 2(21.133,10.615) 3(18.72,10.615) 4(16.307,10.615) 5(13.894,10.615) 6(11.481,10.615) 7(9.068,10.615) 8(6.655,10.615) 9(4.242,10.615) 10(1.829,10.615) 11(-0.584,10.615) 12(-2.997,10.615) 13(-5.41,10.615) 14(-7.823,10.615) 15(-10.236,10.615) 16(-12.649,10.615) 17(-15.062,10.615) 18(-17.475,10.615) 19(-19.888,10.615) 20(-22.301,10.615) 21(-24.714,10.615) 22(24.752,8.075) 23(22.339,8.075) 24(19.926,8.075) 25(17.513,8.075) 26(15.1,8.075) 27(12.687,8.075) 28(10.274,8.075) 29(7.861,8.075) 30(5.448,8.075) 31(3.035,8.075) 32(0.622,8.075) 33(-1.791,8.075) 34(-4.204,8.075) 35(-6.617,8.075) 36(-9.03,8.075) 37(-11.443,8.075) 38(-13.856,8.075) 39(-16.269,8.075) 40(-18.682,8.075) 41(-21.095,8.075) 42(-23.508,8.075) 43(23.546,5.535) 44(21.133,5.535) 45(18.72,5.535) 46(16.307,5.535) 47(13.894,5.535) 48(11.481,5.535) 49(9.068,5.535) 50(6.655,5.535) 51(4.242,5.535) 52(1.829,5.535) 53(-0.584,5.535) 54(-2.997,5.535) 55(-5.41,5.535) 56(-7.823,5.535) 57(-10.236,5.535) 58(-12.649,5.535) 59(-15.062,5.535) 60(-17.475,5.535) 61(-19.888,5.535) 62(-22.301,5.535)
  round 3.81 hole 3.048: 63(-31.75,8.075) 64(31.75,8.075)
DO-214AA_SMB
  rect 2.159x2.286 smd: 1(-2.16,0) 2(2.16,0)
F0603
  rect 0.762x1.092 smd: 1(-0.762,0) 2(0.762,0)
FB0603
  rect 0.762x0.813 smd: 1(-0.762,0) 2(0.762,0)
HD40-2_0-40_19X4_19-H4_44
  rect 1.321x1.321 hole 0.813: 1(-19,-1)
  round 1.321 hole 0.813: 2(-19,1) 3(-17,-1) 4(-17,1) 5(-15,-1) 6(-15,1) 7(-13,-1) 8(-13,1) 9(-11,-1) 10(-11,1) 11(-9,-1) 12(-9,1) 13(-7,-1) 14(-7,1) 15(-5,-1) 16(-5,1) 17(-3,-1) 18(-3,1) 19(-1,-1) 20(-1,1) 21(1,-1) 22(1,1) 23(3,-1) 24(3,1) 25(5,-1) 26(5,1) 27(7,-1) 28(7,1) 29(9,-1) 30(9,1) 31(11,-1) 32(11,1) 33(13,-1) 34(13,1) 35(15,-1) 36(15,1) 37(17,-1) 38(17,1) 39(19,-1) 40(19,1)
HOLE292-174
  round 7.417 hole 4.42: 1(0,0)
HOLE315-157
  round 8.001 hole 3.988: 1(0,0)
IND_74437349047
  rect 2.972x3.505 smd: 1(-2.725,0) 2(2.725,0)
L4-0805
  rect 0.889x0.559 smd: 1(-0.825,-0.4) 2(0.825,-0.4) 3(0.825,0.4) 4(-0.825,0.4)
L1008
  rect 1.397x2.032 smd: 1(-1.27,0) 2(1.27,0)
L7567
  rect 2.007x3.404 smd: 1(-2.9,0) 2(2.9,0)
QFN16-050-0303LH
  oval 0.254x0.762 smd: 1(-0.75,-1.525) 2(-0.25,-1.525) 3(0.25,-1.525) 4(0.75,-1.525) 9(0.75,1.525) 10(0.25,1.525) 11(-0.25,1.525) 12(-0.75,1.525)
  oval 0.762x0.254 smd: 5(1.525,-0.75) 6(1.525,-0.25) 7(1.525,0.25) 8(1.525,0.75) 13(-1.525,0.75) 14(-1.525,0.25) 15(-1.525,-0.25) 16(-1.525,-0.75)
  rect 1.727x1.727 smd: 17(0,0)
QFP64-50-1010L
  rect 1.651x0.254 smd: 1(-5.625,3.75) 2(-5.625,3.25) 3(-5.625,2.75) 4(-5.625,2.25) 5(-5.625,1.75) 6(-5.625,1.25) 7(-5.625,0.75) 8(-5.625,0.25) 9(-5.625,-0.25) 10(-5.625,-0.75) 11(-5.625,-1.25) 12(-5.625,-1.75) 13(-5.625,-2.25) 14(-5.625,-2.75) 15(-5.625,-3.25) 16(-5.625,-3.75) 33(5.625,-3.75) 34(5.625,-3.25) 35(5.625,-2.75) 36(5.625,-2.25) 37(5.625,-1.75) 38(5.625,-1.25) 39(5.625,-0.75) 40(5.625,-0.25) 41(5.625,0.25) 42(5.625,0.75) 43(5.625,1.25) 44(5.625,1.75) 45(5.625,2.25) 46(5.625,2.75) 47(5.625,3.25) 48(5.625,3.75)
  rect 0.254x1.651 smd: 17(-3.75,-5.625) 18(-3.25,-5.625) 19(-2.75,-5.625) 20(-2.25,-5.625) 21(-1.75,-5.625) 22(-1.25,-5.625) 23(-0.75,-5.625) 24(-0.25,-5.625) 25(0.25,-5.625) 26(0.75,-5.625) 27(1.25,-5.625) 28(1.75,-5.625) 29(2.25,-5.625) 30(2.75,-5.625) 31(3.25,-5.625) 32(3.75,-5.625) 49(3.75,5.625) 50(3.25,5.625) 51(2.75,5.625) 52(2.25,5.625) 53(1.75,5.625) 54(1.25,5.625) 55(0.75,5.625) 56(0.25,5.625) 57(-0.25,5.625) 58(-0.75,5.625) 59(-1.25,5.625) 60(-1.75,5.625) 61(-2.25,5.625) 62(-2.75,5.625) 63(-3.25,5.625) 64(-3.75,5.625)
R0402
  rect 0.635x0.508 smd: 1(-0.508,0) 2(0.508,0)
R0805
  rect 0.991x1.194 smd: 1(-1,0) 2(1,0)
R1206
  rect 1.397x1.651 smd: 1(-1.397,0) 2(1.397,0)
SHD10-2_54
  round 1.575 hole 1.575 unplated: (-3.81,0) (3.81,0)
  custom 0.318x0.318 smd: 1(-5.08,-2.22) 2(-5.08,2.22) 3(-2.54,-2.22) 4(-2.54,2.22) 7(2.54,-2.22) 8(2.54,2.22) 9(5.08,-2.22) 10(5.08,2.22)
  rect 1.27x3.683 smd: 5(0,-2.22) 6(0,2.22)
SIP2-2_54
  rect 1.524x1.524 hole 1.016: 1(1.27,0)
  round 1.524 hole 1.016: 2(-1.27,0)
SMA
  rect 2.515x1.702 smd: 1(2,0) 2(-2,0)
SON10-080-0404LH
  oval 0.508x0.813 smd: 1(-1.6,-2) 2(-0.8,-2) 3(0,-2) 4(0.8,-2) 5(1.6,-2) 6(1.6,2) 7(0.8,2) 8(0,2) 9(-0.8,2) 10(-1.6,2)
  rect 3.048x2.642 smd: 11(0,0)
SOP8-50-157
  rect 0.635x1.778 smd: 1(-1.905,-2.7) 2(-0.635,-2.7) 3(0.635,-2.7) 4(1.905,-2.7) 5(1.905,2.7) 6(0.635,2.7) 7(-0.635,2.7) 8(-1.905,2.7)
SOP10-0_5-3_1X3_1H-H1_1
  rect 0.254x1.397 smd: 1(-1,-2.15) 2(-0.5,-2.15) 3(0,-2.15) 4(0.5,-2.15) 5(1,-2.15) 6(1,2.15) 7(0.5,2.15) 8(0,2.15) 9(-0.5,2.15) 10(-1,2.15)
  rect 1.905x1.702 smd: 11(0,0)
SOP14-50-150
  rect 0.635x1.778 smd: 1(-3.81,-2.667) 2(-2.54,-2.667) 3(-1.27,-2.667) 4(0,-2.667) 5(1.27,-2.667) 6(2.54,-2.667) 7(3.81,-2.667) 8(3.81,2.667) 9(2.54,2.667) 10(1.27,2.667) 11(0,2.667) 12(-1.27,2.667) 13(-2.54,2.667) 14(-3.81,2.667)
SOP16-065-4_37
  rect 0.305x1.524 smd: 1(-2.275,-2.921) 2(-1.625,-2.921) 3(-0.975,-2.921) 4(-0.325,-2.921) 5(0.325,-2.921) 6(0.975,-2.921) 7(1.625,-2.921) 8(2.275,-2.921) 9(2.275,2.921) 10(1.625,2.921) 11(0.975,2.921) 12(0.325,2.921) 13(-0.325,2.921) 14(-0.975,2.921) 15(-1.625,2.921) 16(-2.275,2.921)
SOP20-1_27-13_0X7_6-H2_65
  rect 0.635x1.905 smd: 1(-5.715,-4.849) 2(-4.445,-4.849) 3(-3.175,-4.849) 4(-1.905,-4.849) 5(-0.635,-4.849) 6(0.635,-4.849) 7(1.905,-4.849) 8(3.175,-4.849) 9(4.445,-4.849) 10(5.715,-4.849) 11(5.715,4.849) 12(4.445,4.849) 13(3.175,4.849) 14(1.905,4.849) 15(0.635,4.849) 16(-0.635,4.849) 17(-1.905,4.849) 18(-3.175,4.849) 19(-4.445,4.849) 20(-5.715,4.849)
SOT23-3-095-3X1_4
  rect 0.762x1.016 smd: 1(-0.955,-1.05) 2(0.955,-1.05) 3(0,1.05)
SOT23-6-095-2_9X1_6
  rect 0.635x1.143 smd: 1(-0.95,-1.22) 2(0,-1.22) 3(0.95,-1.22) 4(0.95,1.22) 5(0,1.22) 6(-0.95,1.22)
SW4-0403
  rect 1.016x0.762 smd: 1(-2.075,1.075) 2(2.075,1.075) 3(-2.075,-1.075) 4(2.075,-1.075)
TC7343
  rect 2.667x2.413 smd: 1(-3.233,0) 2(3.233,0)
unnamed#2
  round 1.016 smd: 1(0,0)
X2-3225
  rect 1.524x2.794 smd: 1(-1.1,0) 2(1.1,0)

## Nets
GND: C1.2 C3.2 C4.2 C5.2 C6.2 C7.2 C8.2 C9.2 C10.2 C11.2 C12.2 C13.2 C14.2 C16.2 C17.2 C18.2 C19.2 C20.1 C21.2 C22.2 C24.2 C25.1 C26.2 C27.2 C29.2 C30.2 C31.2 C32.2 C33.2 C34.2 C35.2 C36.2 C37.2 C38.2 C39.2 C40.2 C41.2 C42.2 C44.2 C45.2 C46.2 C47.2 C49.2 C50.2 C51.2 C52.2 C53.2 C54.2 C55.2 C57.2 C58.2 C59.1 C60.2 C61.2 C62.2 C63.2 C64.2 C65.2 C66.2 C67.2 C68.2 C69.2 C70.2 C71.2 C72.2 C73.2 C74.2 C75.2 C76.2 C77.2 C78.2 C79.2 C80.2 C81.2 C82.2 C83.2 C84.2 C85.2 C86.2 C87.2 C88.2 C89.2 C90.2 C91.2 C92.2 C93.2 C94.2 C95.2 C96.2 C129.2 C130.2 C131.2 C132.2 C137.2 C138.2 C139.2 C140.2 C145.2 C146.2 C147.2 C148.2 C153.2 C154.2 C155.2 C156.2 C161.2 C162.2 C163.2 C164.2 C169.2 C170.2 C171.2 C172.2 C177.2 C178.2 C179.2 C180.2 C185.2 C186.2 C187.2 C188.2 C193.2 C196.2 C197.2 C198.2 C201.2 C202.2 C203.2 C204.2 C205.2 C206.2 C207.2 C208.2 C209.2 C210.2 C211.2 C212.2 C213.2 C214.2 C215.2 C216.2 C219.2 C220.2 C221.2 C224.2 D1.2 D2.2 D3.2(CATHODEC) D4.2 D5.2 D6.2(CATHODEC) D7.2 D9.1 D10.1 D11.1 D12.1 D13.1 D14.1 D15.2(CATHODEC) D16.3 D17.3 D18.2 D19.3 D20.3 D21.3 D22.3 D23.3 D24.3 D25.3 D26.3 D27.3 D28.3 D29.3 D30.3 D31.3 D32.3 D33.3 D34.3 D35.3 D36.3 D49.3 D50.3 D51.3 D52.3 D53.3 D54.3 J1.4 J1.9 J1.14 J1.15 J1.18 J1.19 J1.24 J1.25 J1.30 J1.35 J1.40 J1.44 J1.49 J1.54 J1.59 J2.1 J2.6 J2.29 J2.30 J2.41 J3.2 J3.4 J3.6 J3.8 J3.9 J3.13 J3.14 J3.15 J3.22 J3.25 J3.32 J3.35 J4.4 J4.7 J4.14 J4.17 J4.24 J4.27 J4.33 J4.35 J4.37 J4.39 J5.2 J5.4 J5.6 J5.8 J5.10 J5.13 J5.14 J5.15 J5.22 J5.25 J5.32 J5.35 J6.4 J6.7 J6.14 J6.17 J6.24 J6.27 J6.33 J6.35 J6.37 J6.39 J9.6(B3) Q1.2(SOURCE) Q2.2(SOURCE) Q3.2(SOURCE) Q4.2(SOURCE) Q5.2(SOURCE) Q6.2(SOURCE) Q7.2(SOURCE) Q8.2(SOURCE) Q9.2(SOURCE) Q10.2(SOURCE) R1.1 R2.1 R7.2 R8.2 R14.2 R15.2 R19.2 R20.2 R23.2 R24.1 R27.1 R30.1 R35.1 R38.2 R42.2 R43.2 R44.2 R49.2 R51.2 R52.1 R57.2 R58.2 R59.2 R62.2 R63.2 R65.2 R67.2 R69.2 R71.2 R73.2 R75.2 R77.2 R78.2 R81.2 R83.2 R86.2 R87.2 R89.2 R92.2 R93.2 R95.2 R97.2 R99.2 R101.2 R103.2 R105.2 R107.2 R110.2 R111.2 R125.2 R127.2 R130.2 R132.2 R135.2 R137.2 R140.2 R142.2 R146.2 R150.2 R153.1 R156.1 R158.2 R160.2 R162.2 R164.2 R165.2 R166.2 R167.2 R171.2 R172.2 R176.2 R177.2 R202.2 SW1.3 SW1.4 U1.8(GND) U1.11(PWR_PAD) U2.5(FB) U2.6(AGND) U2.7(FSW) U2.8(DEF) U2.15(PGND1) U2.16(PGND2) U2.17(PWR_PAD) U3.6(SYNC) U3.11(GND) U4.6(SYNC) U4.11(GND) U5.5(GND) U5.11(GND1) U6.3(PC14/OSC32_IN) U6.12(VSSA/VREF-) U6.18(VSS_4) U6.31(VSS_2) U6.47(VSS_3) U6.63(VSS_1) U7.6(GND) U7.7(GND_1) U8.3(CLK) U8.4(DGND) U8.5(AVSS) U9.5(FB) U9.6(AGND) U9.7(FSW) U9.8(DEF) U9.15(PGND1) U9.16(PGND2) U9.17(PWR_PAD) U10.6(SYNC) U10.11(GND) U11.6(GND) U11.7(GND_1) U12.6(GND) U12.7(GND_1) U13.6(GND) U13.7(GND_1) U14.6(GND) U14.7(GND_1) U15.6(GND) U15.7(GND_1) U16.6(GND) U16.7(GND_1) U17.6(GND) U17.7(GND_1) U18.6(GND) U18.7(GND_1) U19.6(GND) U19.7(GND_1) U20.6(GND) U20.7(GND_1) U21.6(GND) U21.7(GND_1) U22.6(GND) U22.7(GND_1) U23.6(GND) U23.7(GND_1) U24.6(GND) U24.7(GND_1) U25.6(GND) U25.7(GND_1) U26.6(GND) U26.7(GND_1) U27.6(GND) U27.7(GND_1) U28.6(GND) U28.7(GND_1) U33.1(GND1) U33.3(GND2) U33.9(GND3) U33.10(GND4) U34.1(GND1) U34.3(GND2) U34.9(GND3) U34.10(GND4) U35.1(GND1) U35.3(GND2) U35.9(GND3) U35.10(GND4) U36.1(GND1) U36.3(GND2) U36.9(GND3) U36.10(GND4) U37.1(GND1) U37.3(GND2) U37.9(GND3) U37.10(GND4) U38.1(GND1) U38.3(GND2) U38.9(GND3) U38.10(GND4) U39.1(GND1) U39.3(GND2) U39.9(GND3) U39.10(GND4) U40.1(GND1) U40.3(GND2) U40.9(GND3) U40.10(GND4) U41.14(GND) U42.14(GND) U43.1(GND) U44.2 U45.1(GND) U46.2 U47.6(GND) U47.7(GND_1) U48.6(GND) U48.7(GND_1) U49.6(GND) U49.7(GND_1) U50.6(GND) U50.7(GND_1) U51.14(GND) U52.14(GND)
GND_ISO12: C133.2 C134.2 C135.2 C136.2 C141.2 C142.2 C143.2 C144.2 D41.3 D42.3 J2.21 U33.11(GND_ISO1) U33.14(GND_ISO2) U33.16(GND_ISO3) U33.20(GND_ISO4) U34.11(GND_ISO1) U34.14(GND_ISO2) U34.16(GND_ISO3) U34.20(GND_ISO4)
GND_ISO13: C149.2 C150.2 C151.2 C152.2 C157.2 C158.2 C159.2 C160.2 D43.3 D44.3 J2.16 U35.11(GND_ISO1) U35.14(GND_ISO2) U35.16(GND_ISO3) U35.20(GND_ISO4) U36.11(GND_ISO1) U36.14(GND_ISO2) U36.16(GND_ISO3) U36.20(GND_ISO4)
GND_ISO14: C165.2 C166.2 C167.2 C168.2 C173.2 C174.2 C175.2 C176.2 D45.3 D46.3 J2.36 U37.11(GND_ISO1) U37.14(GND_ISO2) U37.16(GND_ISO3) U37.20(GND_ISO4) U38.11(GND_ISO1) U38.14(GND_ISO2) U38.16(GND_ISO3) U38.20(GND_ISO4)
GND_ISO15: C181.2 C182.2 C183.2 C184.2 C189.2 C190.2 C191.2 C192.2 D47.3 D48.3 J2.31 U39.11(GND_ISO1) U39.14(GND_ISO2) U39.16(GND_ISO3) U39.20(GND_ISO4) U40.11(GND_ISO1) U40.14(GND_ISO2) U40.16(GND_ISO3) U40.20(GND_ISO4)
VCC_MAIN: C6.1 C7.1 C61.1 C62.1 C65.1 C66.1 C69.1 C70.1 C73.1 C74.1 C77.1 C78.1 C81.1 C82.1 C85.1 C86.1 C89.1 C90.1 C93.1 C94.1 C204.1 C207.1 C209.1 C211.1 C213.1 FB1.1 FB5.1 J3.1 J3.3 L1.2 R5.1 R6.1 R32.1 R151.2 U11.13(VCC) U11.14(VCC_1) U13.13(VCC) U13.14(VCC_1) U15.13(VCC) U15.14(VCC_1) U17.13(VCC) U17.14(VCC_1) U19.13(VCC) U19.14(VCC_1) U21.13(VCC) U21.14(VCC_1) U23.13(VCC) U23.14(VCC_1) U25.13(VCC) U25.14(VCC_1) U27.13(VCC) U27.14(VCC_1) U43.2(IN) U47.13(VCC) U47.14(VCC_1) U49.13(VCC) U49.14(VCC_1)
VCC_SPARE: C21.1 C206.1 FB2.1 FB6.1 J5.1 J5.3 L3.2 R12.1 R13.1 R26.1 R154.2 U3.1(BD) U45.2(IN)
VDD33_MAIN: C11.1 C193.1 D12.3 D55.2 J3.5 J3.7 L2.2 R9.2 R143.1 R144.1 U2.14(VOS) U6.15(PA1/ADC1_IN2) U41.15(VCC)
VDD33_MAIN_485: C52.1 C129.1 C130.1 C131.1 C132.1 C145.1 C146.1 C147.1 C148.1 C161.1 C162.1 C163.1 C164.1 C177.1 C178.1 C179.1 C180.1 L6.2 R53.2 U9.14(VOS) U33.2(VCC1) U33.8(VCC2) U35.2(VCC1) U35.8(VCC2) U37.2(VCC1) U37.8(VCC2) U39.2(VCC1) U39.8(VCC2)
VDD33_RS232: C216.1 C221.1 D55.3 R178.1 R179.1 R187.2 R188.2 R189.2 R190.1 R191.1 R195.2 R196.2 R197.2 R198.1 R199.1 R203.1 R204.1 U51.15(VCC) U52.15(VCC)
VDD33_SPARE: C26.1 C198.1 D11.3 D55.1 J5.5 J5.7 L4.2 R18.1 R147.1 R148.1 U4.1(BD) U6.10(PC2/ADC12_IN8) U42.15(VCC)
VDD33_SPARE_485: C60.1 C63.1 C64.1 C67.1 C68.1 C71.1 C72.1 C75.1 C76.1 C79.1 C80.1 C83.1 C84.1 C87.1 C88.1 C91.1 C92.1 C95.1 C96.1 C137.1 C138.1 C139.1 C140.1 C153.1 C154.1 C155.1 C156.1 C169.1 C170.1 C171.1 C172.1 C185.1 C186.1 C187.1 C188.1 C208.1 C210.1 C212.1 C214.1 L7.2 R56.1 U10.1(BD) U12.14(VCC_1) U14.14(VCC_1) U16.14(VCC_1) U18.14(VCC_1) U20.14(VCC_1) U22.14(VCC_1) U24.14(VCC_1) U26.14(VCC_1) U28.14(VCC_1) U34.2(VCC1) U34.8(VCC2) U36.2(VCC1) U36.8(VCC2) U38.2(VCC1) U38.8(VCC2) U40.2(VCC1) U40.8(VCC2) U48.14(VCC_1) U50.14(VCC_1)
VDD33_SWITCH: C29.1 C33.1 C37.1 C38.1 C39.1 C40.1 C41.1 C44.1 C45.1 C51.1 D9.2 D10.2 D11.2 D12.2 D13.2 D14.2 FB3.2 FB4.1 J9.2(B1) J9.4(B2) L5.2 R37.1 R39.1 R157.1 R159.1 R161.1 R163.1 U5.1(FB/VOUT) U5.2(OUT) U5.8(BD) U6.1(VBAT) U6.19(VDD_4) U6.32(VDD_2) U6.48(VDD_3) U6.64(VDD_1) U7.14(VCC_1) U8.13(DVDD)
VIN28V_MAIN: D1.1 F1.1 J1.20 J1.21
VIN28V_SPARE: D4.1 F2.1 J1.16 J1.17
VIN_MAIN: C1.1 C3.1 C4.1 C5.1 D8.1 F1.2 R3.1 R21.2 U1.2(VIN)
VIN_MAIN_MONITOR: R21.1 R31.1
VIN_SPARE: C16.1 C17.1 C18.1 C19.1 D8.2 F2.2 R10.1 R22.2 U3.4(VIN)
VIN_SPARE_MONITOR: R22.1 R25.1
A1: D20.1 J1.37 R60.1 U11.12(A) U12.12(A)
A2: D22.1 J1.56 R66.1 U13.12(A) U14.12(A)
A3: D24.1 J1.11 R72.1 U15.12(A) U16.12(A)
A4: D26.1 J1.32 R80.1 U17.12(A) U18.12(A)
A5: D28.1 J1.51 R85.1 U19.12(A) U20.12(A)
A6: D30.1 J1.6 R91.1 U21.12(A) U22.12(A)
A7: D32.1 J1.27 R96.1 U23.12(A) U24.12(A)
A8: D34.1 J1.46 R102.1 U25.12(A) U26.12(A)
A9: D36.1 J1.1 R109.1 U27.12(A) U28.12(A)
A10: D52.1 J2.8 R170.1 U47.12(A) U48.12(A)
A11: D53.1 J2.3 R201.2 R208.2
A_SWITCH: D17.1 J2.42 R45.1 U7.12(A)
B1: D20.2 J1.36 R60.2 U11.11(B) U12.11(B)
B2: D22.2 J1.55 R66.2 U13.11(B) U14.11(B)
B3: D24.2 J1.10 R72.2 U15.11(B) U16.11(B)
B4: D26.2 J1.31 R80.2 U17.11(B) U18.11(B)
B5: D28.2 J1.50 R85.2 U19.11(B) U20.11(B)
B6: D30.2 J1.5 R91.2 U21.11(B) U22.11(B)
B7: D32.2 J1.26 R96.2 U23.11(B) U24.11(B)
B8: D34.2 J1.45 R102.2 U25.11(B) U26.11(B)
B9: D36.2 J1.23 R109.2 U27.11(B) U28.11(B)
B10: D52.2 J2.7 R170.2 U47.11(B) U48.11(B)
B11: D53.2 J2.2 R194.2 R209.2
B_SWITCH: D17.2 J2.28 R45.2 U7.11(B)
BOARD_ID0: R157.2 R158.1 U6.25(PC5)
BOARD_ID1: R159.2 R160.1 U6.26(PB0)
BOARD_ID2: R161.2 R162.1 U6.27(PB1/ADC1_IN12)
BOARD_ID3: R163.2 R164.1 U6.28(PB2/ADC2_IN12)
CON_MAIN_USB_N: J1.62 L8.1 U44.1
CON_MAIN_USB_P: J1.61 L8.4 U44.3
CON_MAIN_VBUS: C203.1 FB7.1 J1.60 U44.5
CON_SPARE_USB_N: J2.15 L9.1 U46.1
CON_SPARE_USB_P: J2.14 L9.4 U46.3
CON_SPARE_VBUS: C205.1 FB8.1 J2.13 U46.5
ID0: J3.10
ID1: J5.9
ID3: J5.11
ID3_2318431: J3.11
ISO_A12: D42.1 J2.23 R124.1 U33.18(A) U34.18(A)
ISO_A13: D44.1 J2.18 R129.1 U35.18(A) U36.18(A)
ISO_A14: D46.1 J2.38 R134.1 U37.18(A) U38.18(A)
ISO_A15: D48.1 J2.33 R139.1 U39.18(A) U40.18(A)
ISO_B12: D42.2 J2.22 R124.2 U33.17(B) U34.17(B)
ISO_B13: D44.2 J2.17 R129.2 U35.17(B) U36.17(B)
ISO_B14: D46.2 J2.37 R134.2 U37.17(B) U38.17(B)
ISO_B15: D48.2 J2.32 R139.2 U39.17(B) U40.17(B)
ISO_Y12: D41.1 J2.25 U33.13(Y) U34.13(Y)
ISO_Y13: D43.1 J2.20 U35.13(Y) U36.13(Y)
ISO_Y14: D45.1 J2.40 U37.13(Y) U38.13(Y)
ISO_Y15: D47.1 J2.35 U39.13(Y) U40.13(Y)
ISO_Z12: D41.2 J2.24 U33.15(Z) U34.15(Z)
ISO_Z13: D43.2 J2.19 U35.15(Z) U36.15(Z)
ISO_Z14: D45.2 J2.39 U37.15(Z) U38.15(Z)
ISO_Z15: D47.2 J2.34 U39.15(Z) U40.15(Z)
MAIN_AD0: J4.40
MAIN_AD1: J4.38
MAIN_AD2: J4.36
MAIN_CAN_RX: J3.17
MAIN_CAN_TX: J3.18
MAIN_ID2: J3.12 R39.2 U6.36(PB15)
MAIN_POWER_EN: Q1.3(DRAIN) R3.2 U1.3(EN)
MAIN_SAFE_MODE_EN_N: J3.16 R1.2 U11.4(DE) U13.4(DE) U15.4(DE) U17.4(DE) U19.4(DE) U21.4(DE) U23.4(DE) U25.4(DE) U27.4(DE) U33.6(DE) U35.6(DE) U37.6(DE) U39.6(DE) U47.4(DE) U49.4(DE)
MAIN_UART_RX0_DEBUG: J3.19 R145.1
MAIN_UART_RX1: J3.23 R61.1 R62.1
MAIN_UART_RX2: J3.26 R67.1 R68.1
MAIN_UART_RX3: J3.28 R73.1 R74.1
MAIN_UART_RX4: J3.30 R78.1 R79.1
MAIN_UART_RX5: J3.31 R84.1 R86.1
MAIN_UART_RX6: J3.34 R90.1 R92.1
MAIN_UART_RX7: J3.38 R97.1 R98.1
MAIN_UART_RX8: J3.40 R103.1 R104.1
MAIN_UART_RX9: J4.8 R108.1 R110.1
MAIN_UART_RX10: J4.9 R165.1 R169.1
MAIN_UART_RX11: J4.11 R174.1 R176.1
MAIN_UART_RX12: J4.15 R123.1
MAIN_UART_RX13: J4.18 R128.1
MAIN_UART_RX14: J4.19 R133.1
MAIN_UART_RX15: J4.21 R138.1
MAIN_UART_RX16: J4.25 R186.1
MAIN_UART_RX17: J4.28 R207.1
MAIN_UART_RX18: J4.29 J6.30
MAIN_UART_RX19: J4.31 R40.1
MAIN_UART_TX0_DEBUG: J3.20 U41.11(T_IN)
MAIN_UART_TX1: J3.21 U11.5(D)
MAIN_UART_TX2: J3.24 U13.5(D)
MAIN_UART_TX3: J3.27 U15.5(D)
MAIN_UART_TX4: J3.29 U17.5(D)
MAIN_UART_TX5: J3.33 U19.5(D)
MAIN_UART_TX6: J3.36 U21.5(D)
MAIN_UART_TX7: J3.37 U23.5(D)
MAIN_UART_TX8: J3.39 U25.5(D)
MAIN_UART_TX9: J4.6 U27.5(D)
MAIN_UART_TX10: J4.10 U47.5(D)
MAIN_UART_TX11: J4.12 U49.5(D)
MAIN_UART_TX12: J4.13 U33.7(TXD)
MAIN_UART_TX13: J4.16 U35.7(TXD)
MAIN_UART_TX14: J4.20 U37.7(TXD)
MAIN_UART_TX15: J4.22 U39.7(TXD)
MAIN_UART_TX16: J4.23 Q3.1(GATE) R190.2
MAIN_UART_TX17: J4.26 Q7.1(GATE) R198.2
MAIN_UART_TX18: J4.30 J6.29
MAIN_UART_TX19: J4.32 U6.52(PC11/UART3_RX)
MAIN_USB_DN: J4.1 L8.2
MAIN_USB_DP: J4.3 L8.3
MAIN_USB_VBUS: FB7.2 J4.2 U43.6(OUT2) U43.7(OUT1)
MAIN_USB_VBUS_EN_N: J4.5 R152.2
NC2: U7.13(NC2) U12.13(NC2) U14.13(NC2) U16.13(NC2) U18.13(NC2) U20.13(NC2) U22.13(NC2) U24.13(NC2) U26.13(NC2) U28.13(NC2) U48.13(NC2) U50.13(NC2)
RS485_DRIVE_EN: R49.1 U6.40(PC9/TIM3_CH4) U7.4(DE)
RX_DEBUG_MAIN: D49.2 J1.41 U41.8(R_IN)
RX_DEBUG_SPARE: D50.2 J2.43 U42.8(R_IN)
SPARE_AD0: J6.40
SPARE_AD1: J6.38
SPARE_AD2: J6.36
SPARE_CAN_RX: J5.17
SPARE_CAN_TX: J5.18
SPARE_ID2: J5.12 R37.2 U6.33(PB12/ADC2_IN13)
SPARE_POWER_EN: C20.2 Q2.3(DRAIN) R10.2 U3.5(RUN/SS)
SPARE_SAFE_MODE_EN_N: J5.16 R2.2 U12.4(DE) U14.4(DE) U16.4(DE) U18.4(DE) U20.4(DE) U22.4(DE) U24.4(DE) U26.4(DE) U28.4(DE) U34.6(DE) U36.6(DE) U38.6(DE) U40.6(DE) U48.4(DE) U50.4(DE)
SPARE_UART_RX0_DEBUG: J5.19 R149.1
SPARE_UART_RX1: J5.23 R64.1
SPARE_UART_RX2: J5.26 R70.1
SPARE_UART_RX3: J5.28 R76.1
SPARE_UART_RX4: J5.30 R82.1
SPARE_UART_RX5: J5.31 R88.1
SPARE_UART_RX6: J5.34 R94.1
SPARE_UART_RX7: J5.38 R100.1
SPARE_UART_RX8: J5.40 R106.1
SPARE_UART_RX9: J6.8 R112.1
SPARE_UART_RX10: J6.9 R168.1
SPARE_UART_RX11: J6.11 R173.1
SPARE_UART_RX12: J6.15 R126.1
SPARE_UART_RX13: J6.18 R131.1
SPARE_UART_RX14: J6.19 R136.1
SPARE_UART_RX15: J6.21 R141.1
SPARE_UART_RX16: J6.25 R185.1
SPARE_UART_RX17: J6.28 R206.1
SPARE_UART_RX19: J6.31 J9.5(A3) U6.55(PB3/JTDO)
SPARE_UART_TX0_DEBUG: J5.20 U42.11(T_IN)
SPARE_UART_TX1: J5.21 U12.5(DI)
SPARE_UART_TX2: J5.24 U14.5(DI)
SPARE_UART_TX3: J5.27 U16.5(DI)
SPARE_UART_TX4: J5.29 U18.5(DI)
SPARE_UART_TX5: J5.33 U20.5(DI)
SPARE_UART_TX6: J5.36 U22.5(DI)
SPARE_UART_TX7: J5.37 U24.5(DI)
SPARE_UART_TX8: J5.39 U26.5(DI)
SPARE_UART_TX9: J6.6 U28.5(DI)
SPARE_UART_TX10: J6.10 U48.5(DI)
SPARE_UART_TX11: J6.12 U50.5(DI)
SPARE_UART_TX12: J6.13 U34.7(TXD)
SPARE_UART_TX13: J6.16 U36.7(TXD)
SPARE_UART_TX14: J6.20 U38.7(TXD)
SPARE_UART_TX15: J6.22 U40.7(TXD)
SPARE_UART_TX16: J6.23 Q5.1(GATE) R191.2
SPARE_UART_TX17: J6.26 Q9.1(GATE) R199.2
SPARE_UART_TX19: J6.32 J9.8(B4) U6.56(PB4/NJRST)
SPARE_USB_DN: J6.1 L9.2
SPARE_USB_DP: J6.3 L9.3
SPARE_USB_VBUS: FB8.2 J6.2 U45.6(OUT2) U45.7(OUT1)
SPARE_USB_VBUS_EN_N: J6.5 R155.2
SPI_CS_N: R28.1 U8.2(*CS)
SPI_MISO: R33.1 U8.15(DOUT/*DRDY)
SPI_MOSI: R34.1 U8.16(DIN)
SPI_SCK: R29.1 U8.1(SCLK)
TCK_MON: J9.10(B5) U6.49(PA14/JTCK)
TDI_MON: J9.7(A4) U6.50(PA15/JTDI)
TMS_MON: J9.9(A5) U6.46(PA13/JTMS)
TX_DEBUG_MAIN: D49.1 J1.42 U41.13(T_OUT)
TX_DEBUG_SPARE: D50.1 J2.44 U42.13(T_OUT)
UART1_RXD: R46.1 U6.43(PA10/UART1_RX)
UART1_TXD: R36.2 U7.5(DI)
VISO_MAIN: C181.1 C182.1 C183.1 C184.1 U39.12(VISO_OUT) U39.19(VISO_IN)
VISO_MAIN_2407607: C133.1 C134.1 C135.1 C136.1 U33.12(VISO_OUT) U33.19(VISO_IN)
VISO_MAIN_2410539: C149.1 C150.1 C151.1 C152.1 U35.12(VISO_OUT) U35.19(VISO_IN)
VISO_MAIN_2413471: C165.1 C166.1 C167.1 C168.1 U37.12(VISO_OUT) U37.19(VISO_IN)
VISO_SPARE: C189.1 C190.1 C191.1 C192.1 U40.12(VISO_OUT) U40.19(VISO_IN)
VISO_SPARE_2408361: C141.1 C142.1 C143.1 C144.1 U34.12(VISO_OUT) U34.19(VISO_IN)
VISO_SPARE_2411293: C157.1 C158.1 C159.1 C160.1 U36.12(VISO_OUT) U36.19(VISO_IN)
VISO_SPARE_2414225: C173.1 C174.1 C175.1 C176.1 U38.12(VISO_OUT) U38.19(VISO_IN)
Y1: D19.2 J1.39 U11.9(Y) U12.9(Y)
Y2: D21.2 J1.58 U13.9(Y) U14.9(Y)
Y3: D23.2 J1.13 U15.9(Y) U16.9(Y)
Y4: D25.2 J1.34 U17.9(Y) U18.9(Y)
Y5: D27.2 J1.53 U19.9(Y) U20.9(Y)
Y6: D29.2 J1.8 U21.9(Y) U22.9(Y)
Y7: D31.2 J1.29 U23.9(Y) U24.9(Y)
Y8: D33.2 J1.48 U25.9(Y) U26.9(Y)
Y9: D35.2 J1.3 U27.9(Y) U28.9(Y)
Y10: D51.2 J2.10 U47.9(Y) U48.9(Y)
Y11: D54.2 J2.5 R193.2 R211.2
Y_SWITCH: D16.2 J2.12 U7.9(Y)
Z1: D19.1 J1.38 U11.10(Z) U12.10(Z)
Z2: D21.1 J1.57 U13.10(Z) U14.10(Z)
Z3: D23.1 J1.12 U15.10(Z) U16.10(Z)
Z4: D25.1 J1.33 U17.10(Z) U18.10(Z)
Z5: D27.1 J1.52 U19.10(Z) U20.10(Z)
Z6: D29.1 J1.7 U21.10(Z) U22.10(Z)
Z7: D31.1 J1.28 U23.10(Z) U24.10(Z)
Z8: D33.1 J1.47 U25.10(Z) U26.10(Z)
Z9: D35.1 J1.2 U27.10(Z) U28.10(Z)
Z10: D51.1 J2.9 U47.10(Z) U48.10(Z)
Z11: D54.1 J2.4 R200.2 R210.2
Z_SWITCH: D16.1 J2.27 U7.10(Z)
N1072360: C34.1 C35.1 C36.1 FB3.1 U6.13(VDDA/VREF+)
N1089979: C32.1 SW1.1 SW1.2 U6.7(RST_N)
N1090446: C31.1 U6.6(OSC_OUT/PF1) Y1.1
N1090465: C30.1 U6.5(OSC_IN/PF0) Y1.2
N1090963: J9.1(A1) R38.1 U6.60(BOOT0)
N1093241: R36.1 U6.42(PA9/UART1_TX)
N1098241: D9.3 R24.2 R25.2 U6.8(PC0/ADC12_IN6)
N1098327: D10.3 R26.2 R27.2 U6.9(PC1/ADC12_IN7)
N1119775: R28.2 U6.20(PA4/SPI1_NSS)
N1119777: R29.2 U6.21(PA5/SPI1_SCK)
N1119779: R34.2 U6.23(PA7/SPI1_MOSI)
N1119811: R41.1 U6.53(PC12)
N1122591: R33.2 U6.22(PA6/SPI1_MISO)
N1152179: R40.2 U6.51(PC10/UART3_TX)
N2171352: R5.2 R8.1 U1.6(FB)
N2171362: C9.1 R4.2 U1.7(COMP)
N2171370: C8.1 R4.1
N2171378: C10.1 U1.4(SS/TR)
N2171394: R7.1 U1.5(RT/CLK)
N2171436: C2.2 D2.1 L1.1 U1.9(SW)
N2171440: C2.1 U1.1(BOOT)
N2172060: D3.1(ATHODE) R6.2
N2173931: C12.1 C13.1 FB1.2 U2.10(AVIN) U2.11(PVIN1) U2.12(PVIN2) U2.13(EN)
N2174013: C14.1 U2.9(SS/TR)
N2174033: L2.1 U2.1(SW1) U2.2(SW2) U2.3(SW3)
N2174285: R9.1 U2.4(PG)
N2320614: J6.34
N2324503: C23.2 D7.1 L4.1 U4.3(SW)
N2324571: C23.1 U4.2(BOOST)
N2324798: R18.2 R20.1 U4.8(FB)
N2325202: R19.1 U4.10(RT)
N2325262: C27.1 R17.2
N2325279: R17.1 U4.9(VC)
N2325487: C24.1 FB2.2 R16.1 U4.4(VIN)
N2326478: C25.2 R16.2 U4.5(RUN/SS)
N2327690: C15.2 D5.1 L3.1 U3.3(SW)
N2327718: C15.1 U3.2(BOOST)
N2327760: R12.2 R15.1 U3.8(FB)
N2327816: R14.1 U3.10(RT)
N2327844: C22.1 R11.2
N2327848: R11.1 U3.9(VC)
N2332877: R23.1 U5.10(RT)
N2333047: C28.1 U5.7(BOOST)
